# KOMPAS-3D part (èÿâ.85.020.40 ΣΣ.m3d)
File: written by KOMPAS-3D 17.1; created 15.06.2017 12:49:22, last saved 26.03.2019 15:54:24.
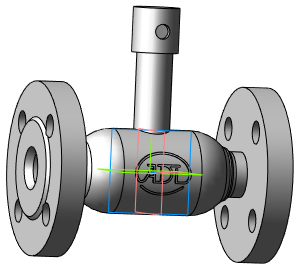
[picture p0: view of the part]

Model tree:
1. Операция без истории:2  (labels: Сталь 20  ГОСТ 1050-88)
